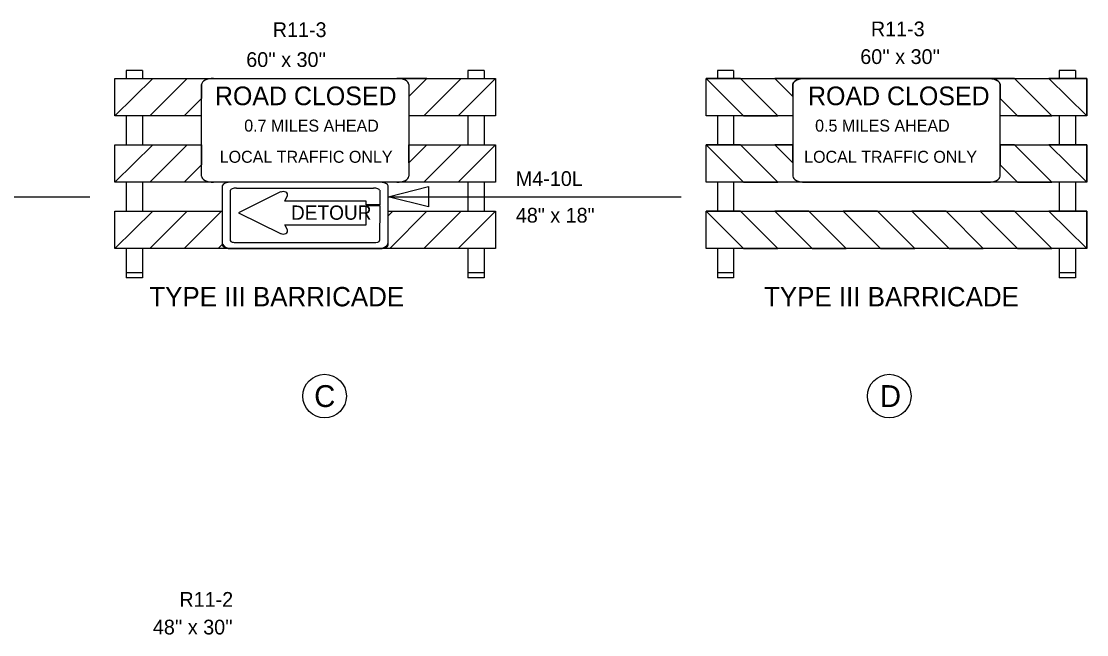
# Model space of a CAD drawing. Extents: x 2157572 to 5059327, y 715220 to 1674494.
# Drawn here: x 2161225 to 2163383, y 720224 to 721465 of the extents above; entities that cross this region are included whole.
import ezdxf

# ---------------------------------------------------------------- set-up
doc = ezdxf.new("R2010")
doc.units = 0
for name, color, linetype in [('Exist Cultural Church Label', 7, 'Continuous'), ('Exist Road Secondary Structure Culvert Number Label', 7, 'Continuous'), ('Level 54', 7, 'Continuous'), ('Map Preparation Border Control Points', 7, 'Continuous'), ('Map Preparation County Base Legend Highway Garage or Maintenance Office', 7, 'Continuous'), ('Map Preparation County Base Legend Lighthouse', 7, 'Continuous'), ('Map Preparation County Inset Control Points', 7, 'Continuous')]:
    doc.layers.add(name, color=color, linetype=linetype)

msp = doc.modelspace()

# ---------------------------------------------------------------- linework, layer by layer
at = {"layer": 'Exist Cultural Church Label'}
for centre in [(2161839.6, 720706.7), (2162983.3, 720706.7)]:
    msp.add_circle(centre, 44.1, dxfattribs=at)
at = {"layer": 'Level 54'}
for p, q in [((2161470.6, 721366), (2161437.9, 721366)), ((2161437.9, 721366), (2161437.9, 721349.7)), ((2161470.6, 721366), (2161470.6, 721349.7)), ((2162162.7, 721366), (2162130, 721366)), ((2162130, 721366), (2162130, 721349.7)), ((2162162.7, 721366), (2162162.7, 721349.7)), ((2161415, 721349.7), (2162185.6, 721349.7)), ((2161415, 721274.1), (2161415, 721349.7)), ((2161415, 721274.1), (2161415, 721349.7)), ((2161415, 721349.7), (2161491.9, 721349.7)), ((2161491.9, 721349.7), (2161415, 721274.1)), ((2161485.7, 721274.1), (2161561.2, 721349.7)), ((2161561.2, 721349.7), (2161614.8, 721349.7)), ((2161590.3, 721337.4), (2161590.3, 721309.4)), ((2162046.9, 721349.7), (2161986, 721349.7)), ((2162010.3, 721313), (2162046.9, 721349.7)), ((2162010.3, 721337.4), (2162010.3, 721313)), ((2162010.3, 721337.4), (2162010.3, 721337.4)), ((2162040.7, 721274.1), (2162116.3, 721349.7)), ((2162185.6, 721349.7), (2162110.1, 721274.1)), ((2162116.3, 721349.7), (2162185.6, 721349.7)), ((2162185.6, 721349.7), (2162185.6, 721274.1)), ((2161590.3, 721309.4), (2161555, 721274.1)), ((2161590.3, 721274.1), (2161415, 721274.1)), ((2161437.9, 721274.1), (2161437.9, 721215.2)), ((2161470.6, 721274.1), (2161470.6, 721215.2)), ((2161555, 721274.1), (2161485.7, 721274.1)), ((2162185.6, 721274.1), (2162010.3, 721274.1)), ((2162110.1, 721274.1), (2162040.7, 721274.1)), ((2162130, 721274.1), (2162130, 721215.2)), ((2162162.7, 721274.1), (2162162.7, 721215.2)), ((2161415, 721139.7), (2161415, 721215.2)), ((2161415, 721139.7), (2161415, 721215.2)), ((2161415, 721215.2), (2161491.9, 721215.2)), ((2161491.9, 721215.2), (2161415, 721139.7)), ((2161415, 721215.2), (2161590.3, 721215.2)), ((2161485.7, 721139.7), (2161561.2, 721215.2)), ((2161561.2, 721215.2), (2161590.3, 721215.2)), ((2162010.3, 721215.2), (2162185.6, 721215.2)), ((2162010.3, 721178.6), (2162010.3, 721215.2)), ((2162010.3, 721215.2), (2162046.9, 721215.2)), ((2162046.9, 721215.2), (2162010.3, 721178.6)), ((2162040.7, 721139.7), (2162116.3, 721215.2)), ((2162185.6, 721215.2), (2162110.1, 721139.7)), ((2162116.3, 721215.2), (2162185.6, 721215.2)), ((2162185.6, 721215.2), (2162185.6, 721139.7)), ((2162185.6, 721139.7), (2161415, 721139.7)), ((2161437.9, 721139.7), (2161437.9, 721080.8)), ((2161470.6, 721139.7), (2161470.6, 721080.8)), ((2161555, 721139.7), (2161485.7, 721139.7)), ((2161648.7, 721021.6), (2161648.7, 721123.4)), ((2161661.2, 721127.6), (2161938.7, 721127.9)), ((2161750.4, 721119.9), (2161665.4, 721077.4)), ((2161951.5, 721123.4), (2161951.5, 721093.6)), ((2162110.1, 721139.7), (2162040.7, 721139.7)), ((2162130, 721139.7), (2162130, 721080.8)), ((2162162.7, 721139.7), (2162162.7, 721080.8)), ((2161759.3, 721101.6), (2161764.2, 721112.5)), ((2161923.6, 721101.6), (2161759.3, 721101.6)), ((2161923.6, 721093.6), (2161923.6, 721101.6)), ((2161968.3, 721110.3), (2162561.7, 721110.3)), ((2161415, 721005.2), (2161415, 721080.8)), ((2161415, 721080.8), (2161491.9, 721080.8)), ((2161491.9, 721080.8), (2161415, 721005.2)), ((2161415, 721005.2), (2161415, 721080.8)), ((2161415, 721080.8), (2161632.3, 721080.8)), ((2161485.7, 721005.2), (2161561.2, 721080.8)), ((2161630.6, 721080.8), (2161555, 721005.2)), ((2161561.2, 721080.8), (2161630.6, 721080.8)), ((2161665.4, 721077.4), (2161750.4, 721035.8)), ((2161951.5, 721093.6), (2161923.6, 721093.6)), ((2161923.6, 721053.7), (2161923.6, 721092.7)), ((2161923.6, 721092.7), (2161951.5, 721092.7)), ((2161951.5, 721092.7), (2161951.1, 721021.6)), ((2161968.3, 721071.5), (2161977.6, 721080.8)), ((2161968.3, 721080.8), (2162185.6, 721080.8)), ((2162046.9, 721080.8), (2161971.4, 721005.2)), ((2161977.6, 721080.8), (2162046.9, 721080.8)), ((2162040.7, 721005.2), (2162116.3, 721080.8)), ((2162185.6, 721080.8), (2162110.1, 721005.2)), ((2162116.3, 721080.8), (2162185.6, 721080.8)), ((2162185.6, 721080.8), (2162185.6, 721005.2)), ((2161968.3, 721017.5), (2161968.3, 721071.5)), ((2161764.2, 721043.1), (2161759.3, 721053.7)), ((2161759.3, 721053.7), (2161923.6, 721053.7)), ((2161624.3, 721005.2), (2161633.1, 721014)), ((2161938.4, 721017.3), (2161661.2, 721017.3)), ((2162185.6, 721005.2), (2161415, 721005.2)), ((2161437.9, 721005.2), (2161437.9, 720946.4)), ((2161470.6, 721005.2), (2161470.6, 720946.4)), ((2161555, 721005.2), (2161485.7, 721005.2)), ((2161651.9, 721005.2), (2161624.3, 721005.2)), ((2161651.9, 721005.2), (2161948.7, 721005.2)), ((2161971.4, 721005.2), (2161948.8, 721005.2)), ((2162110.1, 721005.2), (2162040.7, 721005.2)), ((2162130, 721005.2), (2162130, 720946.4)), ((2162162.7, 721005.2), (2162162.7, 720946.4)), ((2161470.6, 720956.2), (2161437.9, 720956.2)), ((2162162.7, 720956.2), (2162130, 720956.2)), ((2161470.6, 720946.4), (2161437.9, 720946.4)), ((2162162.7, 720946.4), (2162130, 720946.4))]:
    msp.add_line(p, q, dxfattribs=at)
for points in [[(2161590.3, 721151.9), (2161590.3, 721337.4)], [(2161614.8, 721349.7), (2161985.8, 721349.7)], [(2162010.3, 721337.4), (2162010.3, 721151.9)], [(2161590.3, 721215.2), (2161590.3, 721175), (2161555, 721139.7)], [(2161985.8, 721139.7), (2161614.8, 721139.7)], [(2161632.3, 721132.3), (2161632.3, 721012.6)], [(2161948.7, 721139.7), (2161651.9, 721139.7)], [(2161968.3, 721012.6), (2161968.3, 721132.3)]]:
    msp.add_lwpolyline(points, dxfattribs=at)
msp.add_lwpolyline([(2162050.1, 721089.8), (2161968.3, 721110.3), (2162050.1, 721130.7)], close=True, dxfattribs=at)
msp.add_lwpolyline([(2162050.1, 721089.8), (2161968.3, 721110.3), (2162050.1, 721130.7)], close=True, dxfattribs=at)
for centre, major_axis, ratio, start_param, end_param in [((2161614.8, 721337.4), (-24.5, 0), 0.5, 4.712162, 6.283185), ((2161614.8, 721337.4), (-24.5, 0), 0.5, 4.712162, 6.283185), ((2161985.8, 721337.4), (24.5, 0), 0.5, 0, 1.570881), ((2161985.8, 721337.4), (24.5, 0), 0.5, 0, 1.570796), ((2161614.8, 721151.9), (-24.5, 0), 0.5, 0, 1.570796), ((2161985.8, 721151.9), (-24.5, 0), 0.5, 1.570796, 3.141593), ((2161651.9, 721132.3), (-19.6, 0), 0.375009, 4.712389, 6.283185), ((2161661.3, 721123.4), (-12.6, 0), 0.337508, 4.712198, 6.283193), ((2161755.7, 721114.3), (-9, 0), 0.720018, 2.830616, 5.313575), ((2161938.5, 721123.4), (12.6, 0), 0.337508, 6.283183, 7.85379), ((2161948.7, 721132.3), (19.6, 0), 0.375009, 0, 1.571024), ((2161755.7, 721041.1), (-9, 0), 0.720018, 0.969609, 3.452568), ((2161651.9, 721012.6), (19.6, 0), 0.375009, 3.141593, 4.712389), ((2161651.9, 721017.5), (-19.6, 0), 0.625, 0.287132, 1.570688), ((2161661.2, 721021.6), (-12.6, 0), 0.337508, 0.000008, 1.570982), ((2161938.4, 721021.6), (12.6, 0), 0.337508, 4.712575, 6.283183), ((2161948.7, 721017.5), (-19.6, 0), 0.625, 1.570796, 3.141593), ((2161948.7, 721012.6), (19.6, 0), 0.375009, 4.712389, 6.283185)]:
    msp.add_ellipse(centre, major_axis=major_axis, ratio=ratio, start_param=start_param, end_param=end_param, dxfattribs=at)
at = {"layer": 'Map Preparation Border Control Points'}
msp.add_line((2160770.8, 721110.3), (2161364.1, 721110.3), dxfattribs=at)
for points in [[(2162787.9, 721337.4), (2162787.9, 721151.9)], [(2163183.3, 721349.7), (2162812.4, 721349.7)], [(2163207.8, 721151.9), (2163207.8, 721337.4)], [(2162812.4, 721139.7), (2163183.3, 721139.7)], [(2162849.5, 721139.7), (2163146.2, 721139.7)]]:
    msp.add_lwpolyline(points, dxfattribs=at)
for centre, major_axis, start_param, end_param in [((2162812.4, 721337.4), (-24.5, 0), 4.712304, 6.283185), ((2163183.3, 721337.4), (24.5, 0), 0, 1.571024), ((2162812.4, 721151.9), (24.5, 0), 3.141593, 4.712389), ((2163183.3, 721151.9), (24.5, 0), 4.712389, 6.283185)]:
    msp.add_ellipse(centre, major_axis=major_axis, ratio=0.5, start_param=start_param, end_param=end_param, dxfattribs=at)
at = {"layer": 'Map Preparation County Base Legend Highway Garage or Maintenance Office'}
for centre in [(2161839.6, 720706.7), (2162983.3, 720706.7)]:
    msp.add_circle(centre, 44.1, dxfattribs=at)
at = {"layer": 'Map Preparation County Base Legend Lighthouse'}
for p, q in [((2162668.1, 721366), (2162635.4, 721366)), ((2162635.4, 721366), (2162635.4, 721349.7)), ((2162668.1, 721366), (2162668.1, 721349.7)), ((2163360.3, 721366), (2163327.5, 721366)), ((2163327.5, 721366), (2163327.5, 721349.7)), ((2163360.3, 721366), (2163360.3, 721349.7)), ((2162612.5, 721349.7), (2163383.2, 721349.7)), ((2162612.5, 721274.1), (2162612.5, 721349.7)), ((2162681.9, 721349.7), (2162612.5, 721349.7)), ((2162612.5, 721349.7), (2162688.1, 721274.1)), ((2162757.4, 721274.1), (2162681.9, 721349.7)), ((2162820.6, 721349.7), (2162751.2, 721349.7)), ((2162751.2, 721349.7), (2162787.9, 721313)), ((2162812.2, 721349.7), (2162820.6, 721349.7)), ((2163236.9, 721349.7), (2163167.6, 721349.7)), ((2163312.5, 721274.1), (2163236.9, 721349.7)), ((2163383.2, 721349.7), (2163306.3, 721349.7)), ((2163306.3, 721349.7), (2163383.2, 721274.1)), ((2163383.2, 721349.7), (2163383.2, 721274.1)), ((2163383.2, 721274.1), (2163383.2, 721349.7)), ((2162787.9, 721274.1), (2162612.5, 721274.1)), ((2162635.4, 721274.1), (2162635.4, 721215.2)), ((2162668.1, 721274.1), (2162668.1, 721215.2)), ((2162688.1, 721274.1), (2162757.4, 721274.1)), ((2163383.2, 721274.1), (2163207.8, 721274.1)), ((2163243.2, 721274.1), (2163312.5, 721274.1)), ((2163327.5, 721274.1), (2163327.5, 721215.2)), ((2163360.3, 721274.1), (2163360.3, 721215.2)), ((2162612.5, 721139.7), (2162612.5, 721215.2)), ((2162681.9, 721215.2), (2162612.5, 721215.2)), ((2162612.5, 721215.2), (2162688.1, 721139.7)), ((2162612.5, 721215.2), (2162787.9, 721215.2)), ((2162757.4, 721139.7), (2162681.9, 721215.2)), ((2162787.9, 721215.2), (2162751.2, 721215.2)), ((2162751.2, 721215.2), (2162787.9, 721178.6)), ((2162787.9, 721197.4), (2162787.9, 721215.2)), ((2163207.8, 721215.2), (2163383.2, 721215.2)), ((2163312.5, 721139.7), (2163236.9, 721215.2)), ((2163383.2, 721215.2), (2163306.3, 721215.2)), ((2163306.3, 721215.2), (2163383.2, 721139.7)), ((2163383.2, 721215.2), (2163383.2, 721139.7)), ((2163383.2, 721139.7), (2163383.2, 721215.2)), ((2162787.9, 721178.6), (2162787.9, 721197.4)), ((2163207.8, 721175), (2163243.2, 721139.7)), ((2163383.2, 721139.7), (2162612.5, 721139.7)), ((2162635.4, 721139.7), (2162635.4, 721080.8)), ((2162668.1, 721139.7), (2162668.1, 721080.8)), ((2162688.1, 721139.7), (2162757.4, 721139.7)), ((2163243.2, 721139.7), (2163312.5, 721139.7)), ((2163327.5, 721139.7), (2163327.5, 721080.8)), ((2163360.3, 721139.7), (2163360.3, 721080.8)), ((2162681.9, 721080.8), (2162612.5, 721080.8)), ((2162612.5, 721080.8), (2162688.1, 721005.2)), ((2162612.5, 721080.8), (2163383.2, 721080.8)), ((2162612.5, 721005.2), (2162612.5, 721080.8)), ((2162757.4, 721005.2), (2162681.9, 721080.8)), ((2162820.6, 721080.8), (2162751.2, 721080.8)), ((2162751.2, 721080.8), (2162826.8, 721005.2)), ((2162896.1, 721005.2), (2162820.6, 721080.8)), ((2162959.2, 721080.8), (2162889.9, 721080.8)), ((2162889.9, 721080.8), (2162965.5, 721005.2)), ((2163034.8, 721005.2), (2162959.2, 721080.8)), ((2163098.3, 721080.8), (2163028.9, 721080.8)), ((2163028.9, 721080.8), (2163104.5, 721005.2)), ((2163173.8, 721005.2), (2163098.3, 721080.8)), ((2163236.9, 721080.8), (2163167.6, 721080.8)), ((2163167.6, 721080.8), (2163243.2, 721005.2)), ((2163312.5, 721005.2), (2163236.9, 721080.8)), ((2163383.2, 721080.8), (2163306.3, 721080.8)), ((2163306.3, 721080.8), (2163383.2, 721005.2)), ((2163383.2, 721005.2), (2163383.2, 721080.8)), ((2163383.2, 721080.8), (2163383.2, 721005.2)), ((2163383.2, 721005.2), (2162612.5, 721005.2)), ((2162635.4, 721005.2), (2162635.4, 720946.4)), ((2162668.1, 721005.2), (2162668.1, 720946.4)), ((2162688.1, 721005.2), (2162757.4, 721005.2)), ((2162826.8, 721005.2), (2162896.1, 721005.2)), ((2162965.5, 721005.2), (2163034.8, 721005.2)), ((2163104.5, 721005.2), (2163173.8, 721005.2)), ((2163243.2, 721005.2), (2163312.5, 721005.2)), ((2163327.5, 721005.2), (2163327.5, 720946.4)), ((2163360.3, 721005.2), (2163360.3, 720946.4)), ((2162668.1, 720956.2), (2162635.4, 720956.2)), ((2163360.3, 720956.2), (2163327.5, 720956.2)), ((2162668.1, 720946.4), (2162635.4, 720946.4)), ((2163360.3, 720946.4), (2163327.5, 720946.4))]:
    msp.add_line(p, q, dxfattribs=at)
for points in [[(2162787.9, 721313), (2162787.9, 721337.6), (2162788.8, 721340.9), (2162791.4, 721343.8), (2162795, 721346.1), (2162801.1, 721348.3), (2162806.9, 721349.4), (2162812.2, 721349.7)], [(2163167.6, 721349.7), (2163186.6, 721349.5), (2163191.3, 721349), (2163195.5, 721348), (2163198.5, 721347), (2163201.4, 721345.7), (2163203.8, 721344.1), (2163205.7, 721342.4), (2163206.8, 721340.9), (2163207.8, 721337.4), (2163207.8, 721309.4), (2163243.2, 721274.1)], [(2163236.9, 721215.2), (2163207.8, 721215.2), (2163207.8, 721175)]]:
    msp.add_lwpolyline(points, dxfattribs=at)
at = {"layer": 'Map Preparation County Inset Control Points'}
msp.add_lwpolyline([(2162849.5, 721349.7), (2163146.2, 721349.7)], dxfattribs=at)

# ---------------------------------------------------------------- texts
at = {"layer": 'Exist Cultural Church Label'}
for s, p in [('C', (2161818.5, 720684.6)), ('D', (2162964.3, 720684.6))]:
    msp.add_text(s, height=44.3, dxfattribs=at).set_placement(p)
at = {"layer": 'Exist Road Secondary Structure Culvert Number Label'}
for s, p in [('R11-3', (2162946.1, 721435.1)), ("60'' x 30''", (2162924.6, 721379)), ('R11-2', (2161545.5, 720280.2)), ("48'' x 30''", (2161491.8, 720224.2))]:
    msp.add_text(s, height=29.88, dxfattribs=at).set_placement(p)
at = {"layer": 'Level 54'}
for s, height, p in [('R11-3', 29.88, (2161734.6, 721433.5)), ("60'' x 30''", 29.88, (2161680.9, 721373)), ('ROAD CLOSED', 37.785, (2161617.5, 721295.6)), ('ROAD CLOSED', 37.785, (2162818.7, 721295.6)), ('0.7 MILES AHEAD', 24.287, (2161676.8, 721242.1)), ('0.5 MILES AHEAD', 24.287, (2162833.1, 721242.1)), ('LOCAL TRAFFIC ONLY', 24.287, (2161627.1, 721179)), ('LOCAL TRAFFIC ONLY', 24.287, (2162810.9, 721179)), ('M4-10L', 29.88, (2162227, 721132.1)), ('DETOUR', 28.88, (2161771.5, 721063.7)), ('48" x 18"', 29.88, (2162227, 721057.9)), ('TYPE III BARRICADE', 39.25, (2161484.5, 720888.4))]:
    msp.add_text(s, height=height, dxfattribs=at).set_placement(p)
at = {"layer": 'Map Preparation County Base Legend Lighthouse'}
msp.add_text('TYPE III BARRICADE', height=39.25, dxfattribs=at).set_placement((2162729.6, 720888.4))

doc.saveas('drawing.dxf')
